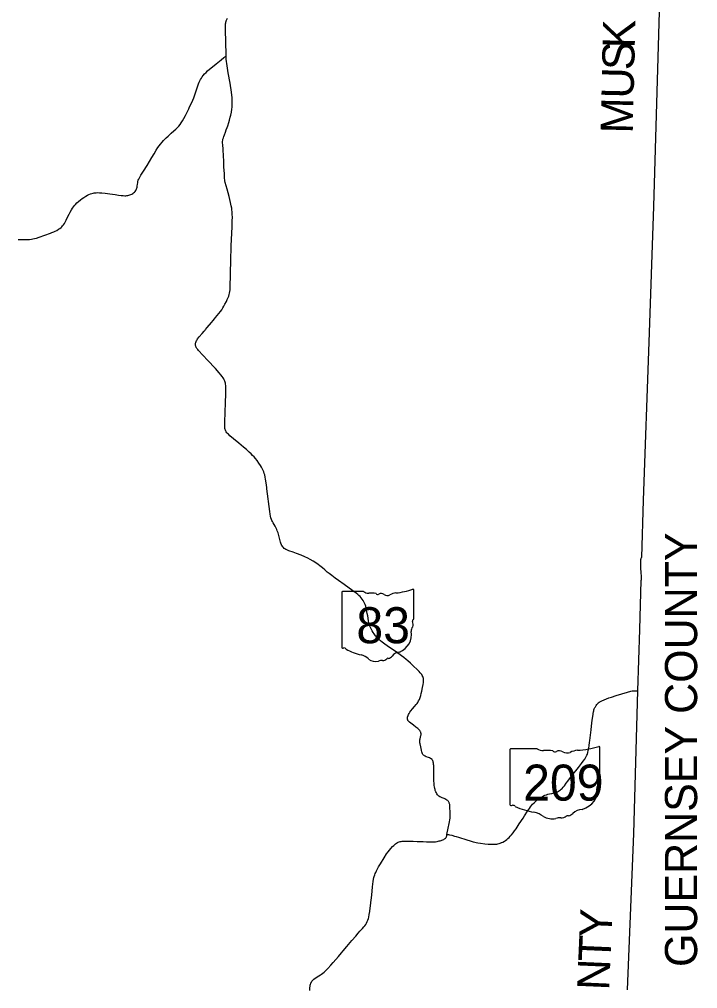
# Model space of a CAD drawing. Extents: x 1913970 to 2287843, y 78841 to 799733.
# Drawn here: x 2182200 to 2203288, y 737859 to 768018 of the extents above; entities that cross this region are included whole.
import ezdxf

# ---------------------------------------------------------------- set-up
doc = ezdxf.new("R2010")
doc.units = 0
for name, color, linetype in [('GM_X_County', 7, 'Continuous'), ('GM_X_County_Text', 7, 'Continuous'), ('GM_X_State_Location', 7, 'Continuous'), ('GM_X_State_Route', 7, 'Continuous'), ('GM_X_State_Shield', 7, 'Continuous')]:
    doc.layers.add(name, color=color, linetype=linetype)

msp = doc.modelspace()

# ---------------------------------------------------------------- linework, layer by layer
at = {"layer": 'GM_X_County'}
msp.add_lwpolyline([(2202153, 770412), (2201913, 762197), (2201774, 757977), (2201599, 753053), (2201548, 751275), (2201535, 751259), (2201527, 751247), (2201523, 751239), (2201518, 751226), (2201514, 751209), (2201511, 751194), (2201509, 751176), (2201509, 751156), (2201510, 751119), (2201511, 751074), (2201513, 751019), (2201516, 750940), (2201524, 750806), (2201531, 750688), (2201534, 750628), (2201532, 750592), (2201531, 750578), (2201529, 750569), (2201526, 750557), (2201479, 749033), (2201419, 747129), (2201296, 742683), (2201102, 737817)], dxfattribs=at)
at = {"layer": 'GM_X_State_Route'}
for points in [[(2188609, 767690), (2188608, 767749), (2188609, 767831), (2188612, 767879), (2188617, 767911), (2188624, 767942), (2188627, 767954)], [(2188627, 767954), (2188634, 767973), (2188652, 768018), (2188669, 768052)], [(2188628, 766868), (2188628, 766930), (2188609, 767690)], [(2182163, 761171), (2182313, 761166), (2182379, 761165), (2182444, 761167), (2182510, 761171), (2182575, 761179), (2182623, 761187), (2182671, 761198), (2182734, 761215), (2182811, 761241), (2183166, 761368), (2183212, 761385), (2183273, 761410), (2183317, 761430), (2183360, 761454), (2183416, 761488), (2183457, 761515), (2183495, 761545), (2183519, 761567), (2183541, 761591), (2183572, 761628), (2183600, 761668), (2183625, 761710), (2183645, 761750), (2183655, 761769), (2183709, 761886), (2183748, 761960), (2183779, 762018), (2183819, 762088), (2183852, 762143), (2183882, 762185), (2183911, 762224), (2183945, 762263), (2183990, 762310), (2184039, 762355), (2184102, 762405), (2184156, 762446), (2184207, 762480), (2184262, 762515), (2184320, 762546), (2184364, 762567), (2184411, 762586), (2184457, 762603), (2184489, 762612), (2184521, 762619), (2184555, 762624), (2184591, 762626), (2184636, 762627), (2184692, 762625), (2184767, 762619), (2184865, 762607), (2185010, 762590), (2185092, 762580), (2185173, 762568), (2185286, 762552), (2185366, 762542), (2185431, 762535), (2185480, 762533), (2185513, 762533), (2185545, 762535), (2185577, 762540), (2185608, 762547), (2185639, 762557), (2185669, 762569), (2185697, 762584), (2185725, 762601), (2185750, 762620), (2185775, 762642), (2185795, 762663), (2185816, 762690), (2185833, 762718), (2185846, 762744), (2185853, 762762), (2185861, 762793), (2185866, 762824), (2185872, 762886), (2185880, 762937), (2185885, 762969), (2185897, 763012), (2185911, 763048), (2185930, 763089), (2185951, 763126), (2185978, 763171), (2186056, 763292), (2186169, 763471), (2186320, 763720), (2186387, 763833), (2186455, 763945), (2186508, 764029), (2186545, 764083), (2186585, 764135), (2186638, 764198), (2186681, 764245), (2186704, 764271), (2186762, 764330), (2186822, 764387), (2186920, 764474), (2187006, 764549), (2187066, 764605), (2187112, 764652), (2187156, 764700), (2187197, 764751), (2187235, 764804), (2187270, 764859), (2187311, 764930), (2187365, 765032), (2187416, 765134), (2187465, 765238), (2187493, 765297), (2187558, 765430), (2187591, 765505), (2187622, 765580), (2187656, 765673), (2187688, 765766), (2187738, 765922), (2187770, 766015), (2187789, 766061), (2187809, 766106), (2187832, 766150), (2187858, 766192), (2187886, 766233), (2187916, 766272), (2187958, 766323), (2188003, 766370), (2188051, 766416), (2188113, 766469), (2188203, 766542), (2188318, 766635), (2188470, 766759), (2188558, 766833), (2188576, 766846), (2188591, 766856), (2188607, 766862), (2188628, 766868)], [(2188533, 763998), (2188532, 764015), (2188526, 764080), (2188522, 764118), (2188519, 764175), (2188520, 764215), (2188524, 764258), (2188530, 764290), (2188542, 764331), (2188555, 764371), (2188573, 764421), (2188604, 764505), (2188634, 764585), (2188659, 764649), (2188681, 764710), (2188714, 764808), (2188735, 764881), (2188759, 764972), (2188774, 765036), (2188792, 765133), (2188794, 765142), (2188805, 765214), (2188814, 765296), (2188820, 765378), (2188821, 765460), (2188820, 765542), (2188817, 765592), (2188810, 765657), (2188797, 765755), (2188751, 766030), (2188696, 766353), (2188671, 766499), (2188647, 766644), (2188637, 766710), (2188631, 766782), (2188629, 766837), (2188628, 766868)], [(2190345, 751684), (2190342, 751691), (2190323, 751754), (2190266, 751959), (2190242, 752038), (2190220, 752100), (2190201, 752146), (2190180, 752191), (2190149, 752249), (2190087, 752356), (2190068, 752390), (2190051, 752423), (2190037, 752457), (2190020, 752511), (2190009, 752559), (2189996, 752623), (2189984, 752704), (2189898, 753412), (2189896, 753437), (2189894, 753453), (2189874, 753600), (2189856, 753713), (2189844, 753778), (2189828, 753842), (2189814, 753889), (2189797, 753936), (2189778, 753981), (2189750, 754041), (2189727, 754084), (2189693, 754141), (2189647, 754209), (2189590, 754289), (2189539, 754354), (2189497, 754405), (2189452, 754453), (2189405, 754499), (2189345, 754555), (2189258, 754630), (2189170, 754704), (2189020, 754831), (2188857, 754969), (2188745, 755065), (2188697, 755109), (2188674, 755132), (2188653, 755157), (2188634, 755181), (2188620, 755202), (2188606, 755232), (2188599, 755256), (2188592, 755287), (2188587, 755319), (2188584, 755351), (2188584, 755398), (2188584, 755414), (2188586, 755482), (2188595, 755794), (2188605, 756089), (2188615, 756367), (2188620, 756574), (2188619, 756621), (2188613, 756663), (2188607, 756696), (2188598, 756728), (2188587, 756759), (2188568, 756805), (2188552, 756834), (2188535, 756862), (2188507, 756903), (2188467, 756955), (2188413, 757018), (2188294, 757153), (2188217, 757238), (2188127, 757334), (2188060, 757405), (2187905, 757575), (2187771, 757720), (2187750, 757744), (2187738, 757756), (2187729, 757769), (2187718, 757782), (2187709, 757795), (2187701, 757809), (2187693, 757823), (2187687, 757838), (2187682, 757852), (2187678, 757868), (2187675, 757884), (2187674, 757900), (2187674, 757916), (2187676, 757931), (2187678, 757947), (2187682, 757963), (2187692, 757993), (2187707, 758022), (2187724, 758050), (2187743, 758076), (2187795, 758139), (2187880, 758239), (2187944, 758313), (2187972, 758346), (2187987, 758364), (2188039, 758426), (2188174, 758589), (2188226, 758652), (2188267, 758702), (2188298, 758740), (2188351, 758803), (2188403, 758867), (2188453, 758932), (2188491, 758985), (2188526, 759040), (2188560, 759097), (2188592, 759154), (2188637, 759242), (2188665, 759301), (2188691, 759361), (2188708, 759407), (2188723, 759454), (2188734, 759503), (2188743, 759551), (2188749, 759600), (2188752, 759649), (2188758, 759830), (2188760, 759944), (2188766, 760190), (2188772, 760453), (2188776, 760584), (2188779, 760698), (2188780, 760764), (2188787, 760977), (2188805, 761370), (2188814, 761567), (2188820, 761747), (2188822, 761862), (2188821, 761944), (2188816, 762026), (2188809, 762092), (2188801, 762141), (2188786, 762221), (2188764, 762318), (2188718, 762509), (2188689, 762620), (2188657, 762737), (2188603, 762943), (2188593, 762992), (2188586, 763030), (2188580, 763070), (2188579, 763109), (2188576, 763142), (2188573, 763217), (2188562, 763429), (2188553, 763655), (2188550, 763720), (2188545, 763834), (2188541, 763900), (2188538, 763949), (2188533, 763998)], [(2195494, 742655), (2195504, 742708), (2195523, 742805), (2195576, 743045), (2195588, 743109), (2195594, 743158), (2195598, 743208), (2195598, 743257), (2195593, 743372), (2195589, 743470), (2195582, 743559), (2195579, 743585), (2195573, 743610), (2195566, 743632), (2195561, 743647), (2195553, 743663), (2195545, 743677), (2195534, 743693), (2195519, 743709), (2195496, 743727), (2195480, 743736), (2195457, 743749), (2195432, 743761), (2195406, 743771), (2195345, 743795), (2195300, 743814), (2195272, 743830), (2195246, 743848), (2195222, 743870), (2195201, 743894), (2195182, 743920), (2195165, 743948), (2195151, 743978), (2195133, 744023), (2195123, 744054), (2195115, 744085), (2195105, 744133), (2195099, 744182), (2195092, 744247), (2195087, 744312), (2195084, 744406), (2195083, 744427), (2195084, 744560), (2195082, 744744), (2195082, 744799), (2195081, 744834), (2195076, 744872), (2195071, 744908), (2195066, 744923), (2195060, 744942), (2195051, 744959), (2195040, 744973), (2195031, 744985), (2195008, 745006), (2194984, 745023), (2194951, 745037), (2194923, 745047), (2194851, 745074), (2194822, 745088), (2194794, 745104), (2194782, 745114), (2194769, 745124), (2194758, 745135), (2194748, 745147), (2194739, 745160), (2194731, 745174), (2194724, 745189), (2194719, 745204), (2194714, 745219), (2194701, 745283), (2194679, 745378), (2194658, 745474), (2194653, 745505), (2194651, 745537), (2194651, 745570), (2194655, 745602), (2194660, 745634), (2194687, 745738), (2194690, 745761), (2194690, 745778), (2194690, 745795), (2194687, 745811), (2194685, 745826), (2194679, 745842), (2194674, 745854), (2194666, 745871), (2194656, 745887), (2194644, 745901), (2194619, 745926), (2194594, 745948), (2194529, 745998), (2194450, 746056), (2194370, 746114), (2194328, 746149), (2194302, 746177), (2194293, 746190), (2194283, 746207), (2194277, 746222), (2194272, 746237), (2194269, 746252), (2194267, 746268), (2194267, 746284), (2194269, 746299), (2194272, 746315), (2194276, 746331), (2194286, 746361), (2194300, 746390), (2194315, 746419), (2194341, 746460), (2194370, 746499), (2194422, 746562), (2194487, 746635), (2194541, 746697), (2194571, 746736), (2194589, 746763), (2194615, 746812), (2194638, 746856), (2194662, 746919), (2194679, 746975), (2194696, 747038), (2194715, 747118), (2194739, 747231), (2194757, 747327), (2194766, 747382), (2194770, 747425), (2194770, 747457), (2194767, 747480), (2194763, 747503), (2194762, 747510), (2194752, 747543), (2194740, 747571), (2194726, 747603), (2194710, 747631), (2194692, 747657), (2194665, 747688), (2194632, 747724), (2194566, 747790), (2194459, 747893), (2194363, 747982), (2194277, 748058), (2194228, 748101), (2194151, 748163), (2194085, 748212), (2193924, 748325), (2193762, 748438), (2193709, 748475), (2193562, 748580), (2193483, 748637), (2193431, 748678), (2193394, 748710), (2193362, 748740), (2193324, 748778), (2193292, 748815), (2193275, 748839), (2193232, 748896), (2193204, 748938), (2193168, 748997), (2193125, 749076), (2193117, 749096), (2193098, 749141), (2193081, 749192), (2193069, 749243), (2193057, 749304), (2193031, 749455), (2193018, 749536), (2192998, 749649), (2192989, 749689), (2192984, 749713), (2192971, 749761), (2192954, 749808), (2192935, 749853), (2192912, 749897), (2192886, 749939), (2192858, 749980), (2192827, 750019), (2192794, 750056), (2192758, 750090), (2192721, 750123), (2192669, 750163), (2192564, 750242), (2192298, 750434), (2192125, 750559), (2192019, 750636), (2191914, 750714), (2191834, 750772), (2191769, 750822), (2191693, 750889), (2191625, 750949), (2191544, 751017), (2191485, 751061), (2191414, 751113), (2191337, 751161), (2191242, 751215), (2191169, 751250), (2191079, 751291), (2190959, 751343), (2190821, 751397), (2190714, 751437), (2190574, 751486), (2190513, 751509), (2190484, 751523), (2190456, 751539), (2190431, 751559), (2190408, 751581), (2190387, 751606), (2190369, 751633), (2190354, 751661), (2190345, 751684)], [(2195494, 742655), (2195504, 742655), (2195519, 742654), (2195538, 742653), (2195574, 742646), (2195643, 742632), (2195730, 742607), (2195778, 742595), (2195857, 742572), (2196115, 742487), (2196212, 742455), (2196306, 742425), (2196358, 742412), (2196403, 742401), (2196452, 742393), (2196533, 742383), (2196673, 742366), (2196778, 742359), (2196864, 742355), (2196934, 742352), (2196991, 742352), (2197032, 742356), (2197050, 742357), (2197080, 742363), (2197116, 742373), (2197153, 742386), (2197193, 742402), (2197203, 742407), (2197234, 742421), (2197281, 742450), (2197311, 742471), (2197354, 742501), (2197388, 742529), (2197428, 742565), (2197462, 742601), (2197500, 742643), (2197552, 742707), (2197595, 742768), (2197643, 742835), (2197743, 742985), (2197861, 743162), (2197907, 743231), (2198004, 743382), (2198058, 743464), (2198096, 743518), (2198126, 743557), (2198158, 743594), (2198204, 743642), (2198252, 743686), (2198302, 743729), (2198368, 743779), (2198409, 743807), (2198451, 743832), (2198495, 743855), (2198540, 743875), (2198587, 743893), (2198634, 743908), (2198682, 743920), (2198755, 743935), (2198816, 743949), (2198865, 743962), (2198899, 743972), (2198936, 743986), (2198968, 744005), (2198996, 744023), (2199023, 744042), (2199048, 744063), (2199074, 744089), (2199108, 744126), (2199146, 744173), (2199198, 744247), (2199249, 744311), (2199306, 744388), (2199367, 744466), (2199454, 744577), (2199498, 744631), (2199547, 744687), (2199589, 744738), (2199676, 744859), (2199735, 744936), (2199782, 745002), (2199803, 745037), (2199827, 745080), (2199847, 745124), (2199860, 745157), (2199874, 745202), (2199888, 745264), (2199905, 745342), (2199920, 745426), (2199931, 745514), (2199940, 745578), (2199977, 745911), (2200002, 746125), (2200023, 746274), (2200036, 746388), (2200040, 746420), (2200049, 746468), (2200050, 746474), (2200057, 746501), (2200066, 746532), (2200076, 746561), (2200095, 746603), (2200109, 746632), (2200130, 746666), (2200152, 746696), (2200176, 746723), (2200183, 746730), (2200200, 746747), (2200232, 746771), (2200267, 746793), (2200311, 746817), (2200378, 746848), (2200452, 746878), (2200528, 746905), (2200607, 746931), (2200754, 746977), (2201109, 747082), (2201215, 747113), (2201253, 747122), (2201284, 747126), (2201325, 747129), (2201361, 747129), (2201404, 747128), (2201420, 747126)], [(2193182, 741027), (2193202, 741190), (2193214, 741270), (2193223, 741318), (2193232, 741350), (2193248, 741396), (2193266, 741441), (2193280, 741470), (2193309, 741529), (2193370, 741644), (2193427, 741744), (2193539, 741925), (2193619, 742049), (2193666, 742116), (2193706, 742168), (2193748, 742218), (2193803, 742278), (2193838, 742313), (2193874, 742346), (2193899, 742366), (2193925, 742385), (2193953, 742401), (2193982, 742415), (2194012, 742427), (2194043, 742436), (2194075, 742442), (2194107, 742446), (2194139, 742448), (2194171, 742449), (2194236, 742448), (2194417, 742445), (2194449, 742444), (2194564, 742442), (2194629, 742440), (2194712, 742437), (2194760, 742435), (2194858, 742431), (2195038, 742425), (2195071, 742424), (2195104, 742425), (2195137, 742428), (2195186, 742436), (2195217, 742445), (2195256, 742455), (2195282, 742462), (2195364, 742490), (2195393, 742503), (2195423, 742517), (2195439, 742526), (2195452, 742539), (2195455, 742543), (2195462, 742552), (2195470, 742565), (2195476, 742580), (2195482, 742596), (2195486, 742611), (2195494, 742655)], [(2191229, 737803), (2191235, 737885), (2191240, 737934), (2191246, 737967), (2191253, 737999), (2191258, 738015), (2191262, 738026), (2191266, 738035), (2191278, 738060), (2191295, 738089), (2191305, 738102), (2191316, 738115), (2191328, 738127), (2191334, 738133), (2191356, 738153), (2191394, 738184), (2191445, 738214), (2191462, 738225), (2191515, 738255), (2191563, 738286), (2191597, 738313), (2191636, 738343), (2191674, 738375), (2191734, 738431), (2191791, 738490), (2191880, 738587), (2191957, 738672), (2192043, 738770), (2192119, 738857), (2192214, 738969), (2192267, 739032), (2192381, 739172), (2192541, 739359), (2192659, 739495), (2192735, 739581), (2192790, 739642), (2192866, 739727), (2192909, 739777), (2192939, 739816), (2192968, 739857), (2192993, 739899), (2193016, 739943), (2193035, 739989), (2193051, 740036), (2193063, 740084), (2193080, 740164), (2193096, 740261), (2193111, 740375), (2193117, 740424), (2193128, 740538), (2193144, 740685), (2193154, 740782), (2193168, 740896), (2193182, 741027)]]:
    msp.add_lwpolyline(points, dxfattribs=at)
at = {"layer": 'GM_X_State_Shield'}
for p, q in [((2192222, 750187), (2192222, 748486)), ((2192901, 750216), (2192244, 750216)), ((2194464, 749369), (2194464, 750258)), ((2194463, 749369), (2194464, 749369)), ((2197451, 745290), (2197451, 743589)), ((2198299, 745320), (2197478, 745320)), ((2200252, 744472), (2200252, 745362)), ((2200252, 744472), (2200252, 744472))]:
    msp.add_line(p, q, dxfattribs=at)
for centre, radius, start, end in [((2192248, 750191), 26, 98.1301, 188.1301), ((2193057, 750414), 252, 231.6195, 271.1119), ((2193141, 749261), 904, 80.4867, 94.9883), ((2193346, 750199), 72.7, 219.7921, 297.1024), ((2193452, 750003), 151, 54.4667, 119.1411), ((2193647, 750273), 182, 233.8562, 294.8282), ((2193968, 749697), 478, 97.3462, 120.7689), ((2193665, 752536), 2377, 275.8445, 288.9065), ((2194439, 750262), 25, 351.8621, 97.738), ((2194458, 749303), 38.6, 107.944, 210.337), ((2194212, 749191), 232, 340.033, 23.6496), ((2194437, 749365), 26.7, 289.6038, 7.7341), ((2193798, 748883), 595, 292.3089, 8.9858), ((2194553, 748996), 169, 136.8065, 186.9296), ((2192248, 748482), 26.2, 171.9584, 258.3066), ((2192252, 748656), 200, 267.339, 280.6039), ((2192293, 748388), 72.1, 29.7484, 93.2717), ((2193203, 749916), 1716, 240.4129, 257.1985), ((2194049, 748008), 326, 94.4031, 142.5768), ((2192691, 747722), 537, 47.1842, 75.836), ((2193272, 748379), 341, 230.7004, 286.2918), ((2193469, 747791), 280, 85.6951, 111.2099), ((2193494, 748252), 182, 268.777, 315.5493), ((2193658, 748087), 51.1, 65.7517, 132.6484), ((2193637, 748321), 192, 282.8732, 323.2771)]:
    msp.add_arc(centre, radius, start, end, dxfattribs=at)
for centre, major_axis, start_param, end_param in [((2197483, 745294), (32.5, 0), 1.712693, 3.28349), ((2198494, 745517), (315, 0), 4.042523, 4.731795), ((2198598, 744365), (1130, 0), 1.404758, 1.657858), ((2198855, 745303), (90.8, 0), 3.836095, 5.185415), ((2198988, 745106), (189, 0), 0.950623, 2.079405), ((2199232, 745376), (227, 0), 4.081561, 5.145723), ((2199633, 744800), (598, 0), 1.699011, 2.107814), ((2199254, 747639), (2971, 0), 4.814394, 5.042369), ((2200221, 745365), (31.2, 0), 6.141152, 7.989035), ((2200245, 744407), (48.3, 0), 1.883978, 3.671073), ((2199938, 744294), (290, 0), 5.934695, 6.695948), ((2200219, 744468), (33.4, 0), 5.05454, 6.418171), ((2199421, 743986), (743, 0), 5.101752, 6.440018), ((2200364, 744099), (211, 0), 2.387724, 3.262537), ((2197483, 743585), (32.7, 0), 3.00124, 4.508301), ((2197488, 743759), (250, 0), 4.665946, 4.897461), ((2197539, 743491), (90.1, 0), 0.519207, 1.627899), ((2198677, 745019), (2146, 0), 4.195997, 4.488961), ((2199734, 743112), (407, 0), 1.647645, 2.488434), ((2198037, 742825), (671, 0), 0.823519, 1.323587), ((2198763, 743483), (426, 0), 4.026481, 4.996735), ((2199009, 742894), (350, 0), 1.495662, 1.94098), ((2199040, 743355), (227, 0), 4.691044, 5.507374), ((2199246, 743190), (63.9, 0), 1.147584, 2.315152), ((2199218, 743424), (240, 0), 4.937069, 5.64225)]:
    msp.add_ellipse(centre, major_axis=major_axis, ratio=0.8, start_param=start_param, end_param=end_param, dxfattribs=at)

# ---------------------------------------------------------------- texts
at = {"layer": 'GM_X_County_Text'}
for s, rotation, p in [('K', 88.5993, (2201332, 767108)), ('S', 88.6929, (2201316, 766431)), ('U', 88.6907, (2201296, 765547)), ('M', 88.692, (2201271, 764460)), ('GUERNSEY COUNTY', 90, (2203274, 738531)), ('Y', 87.501, (2200607, 739425)), ('T', 87.4973, (2200575, 738677)), ('N', 87.5004, (2200536, 737794))]:
    msp.add_text(s, height=1000, rotation=rotation, dxfattribs=at).set_placement(p)
at = {"layer": 'GM_X_State_Location'}
for s, p in [('93', (2182675, 761134)), ('83', (2192878, 748779)), ('209', (2198691, 743868))]:
    msp.add_text(s, height=1, rotation=0, dxfattribs=at).set_placement(p)
for s, p in [('s', (2182927, 761207)), ('r', (2182927, 761207)), ('s', (2193130, 748852)), ('r', (2193130, 748852)), ('s', (2199044, 743941)), ('r', (2199044, 743941))]:
    msp.add_text(s, height=1, dxfattribs=at).set_placement(p)
at = {"layer": 'GM_X_State_Shield'}
for s, p in [('83', (2192678, 748606)), ('209', (2197863, 743709))]:
    msp.add_text(s, height=1120.7, dxfattribs=at).set_placement(p)

doc.saveas('drawing.dxf')
